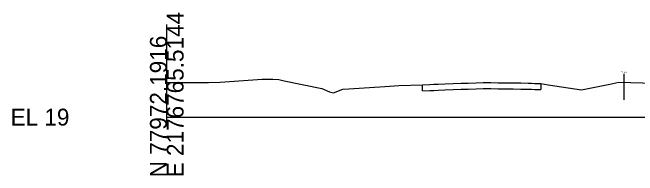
# Model space of a CAD drawing. Extents: x 2177029 to 2201446, y 59897 to 78390.
# Drawn here: x 2200017 to 2200121.1, y 69397.6 to 69424.7 of the extents above; entities that cross this region are included whole.
import ezdxf

# ---------------------------------------------------------------- set-up
doc = ezdxf.new("R2010")
doc.units = 0
for name, color, linetype in [('Exist Cross Section Cell', 7, 'Continuous'), ('Exist XS Ground Line', 7, 'Continuous'), ('Old_Level_3', 7, 'Continuous'), ('Prop CMT Pvmt Wedge Surface 1', 7, 'Continuous'), ('Prop CMT Top Wall Envelope', 7, 'Continuous'), ('Prop XS Earthwork Shape', 7, 'Continuous')]:
    doc.layers.add(name, color=color, linetype=linetype)

msp = doc.modelspace()

# ---------------------------------------------------------------- linework, layer by layer
at = {"layer": 'Exist Cross Section Cell'}
msp.add_line((2200042.73, 69407.31), (2200242.73, 69407.31), dxfattribs=at)
at = {"layer": 'Exist XS Ground Line'}
msp.add_lwpolyline([(2200042.73, 69413.08), (2200049.67, 69413.08), (2200051.63, 69413.13), (2200058.62, 69413.63), (2200060.39, 69413.61), (2200061.38, 69413.56), (2200062.26, 69413.34), (2200068.56, 69412.06), (2200069.81, 69411.53), (2200070.47, 69411.36), (2200072.04, 69411.97), (2200073.06, 69412.03), (2200079.03, 69412.41), (2200081.35, 69412.59), (2200085.3, 69412.68), (2200086.52, 69412.74), (2200087.22, 69412.76), (2200087.9, 69412.79), (2200089.01, 69412.83), (2200090.4, 69412.89), (2200091.75, 69412.93), (2200092.9, 69412.97), (2200094.23, 69413), (2200095.4, 69413.04), (2200096.7, 69413.04), (2200097.9, 69413.03), (2200099.18, 69413.02), (2200100.4, 69413.01), (2200101.66, 69412.98), (2200102.9, 69412.96), (2200103.49, 69412.94), (2200104.04, 69412.92), (2200105.02, 69412.88), (2200106.24, 69412.68), (2200111.81, 69411.82), (2200116.49, 69412.78), (2200118, 69413.09), (2200123.89, 69412.97)], dxfattribs=at)
at = {"layer": 'Old_Level_3'}
msp.add_line((2200042.73, 69405.94), (2200042.73, 69422.68), dxfattribs=at)
at = {"layer": 'Prop CMT Pvmt Wedge Surface 1'}
for p, q in [((2200085.3, 69411.68), (2200085.3, 69412.68)), ((2200105.02, 69412.88), (2200105.02, 69411.88)), ((2200085.3, 69411.68), (2200086.52, 69411.74)), ((2200086.52, 69411.74), (2200087.22, 69411.76)), ((2200087.22, 69411.76), (2200087.9, 69411.79)), ((2200087.9, 69411.79), (2200089.01, 69411.83)), ((2200089.01, 69411.83), (2200090.4, 69411.89)), ((2200090.4, 69411.89), (2200091.75, 69411.93)), ((2200091.75, 69411.93), (2200092.9, 69411.97)), ((2200092.9, 69411.97), (2200094.23, 69412)), ((2200094.23, 69412), (2200095.4, 69412.04)), ((2200095.4, 69412.04), (2200096.7, 69412.04)), ((2200096.7, 69412.04), (2200097.9, 69412.03)), ((2200097.9, 69412.03), (2200099.18, 69412.02)), ((2200099.18, 69412.02), (2200100.4, 69412.01)), ((2200100.4, 69412.01), (2200101.66, 69411.98)), ((2200101.66, 69411.98), (2200102.9, 69411.96)), ((2200102.9, 69411.96), (2200103.49, 69411.94)), ((2200103.49, 69411.94), (2200104.04, 69411.92)), ((2200104.04, 69411.92), (2200105.02, 69411.88))]:
    msp.add_line(p, q, dxfattribs=at)
at = {"layer": 'Prop XS Earthwork Shape'}
msp.add_line((2200118.83, 69414.5), (2200118.83, 69410.2), dxfattribs=at)

# ---------------------------------------------------------------- texts
at = {"layer": 'Exist Cross Section Cell'}
for s, p in [('E 2176765.5144', (2200045.53, 69397.31)), ('N 77972.1916', (2200042.73, 69397.31))]:
    msp.add_text(s, height=2.8, rotation=90, dxfattribs=at).set_placement(p)
msp.add_text('EL 19', height=2.8, dxfattribs=at).set_placement((2200016.73, 69405.91))
at = {"layer": 'Prop CMT Top Wall Envelope'}
msp.add_text('-', height=0.0001, dxfattribs=at).set_placement((2200042.73, 69407.31))
msp.add_text('-', height=0.0001, dxfattribs=at).set_placement((2200042.73, 69407.31))
at = {"layer": 'Prop XS Earthwork Shape'}
msp.add_text('EX. S.S.', height=0.2, dxfattribs=at).set_placement((2200118.34, 69414.64))

doc.saveas('drawing.dxf')
